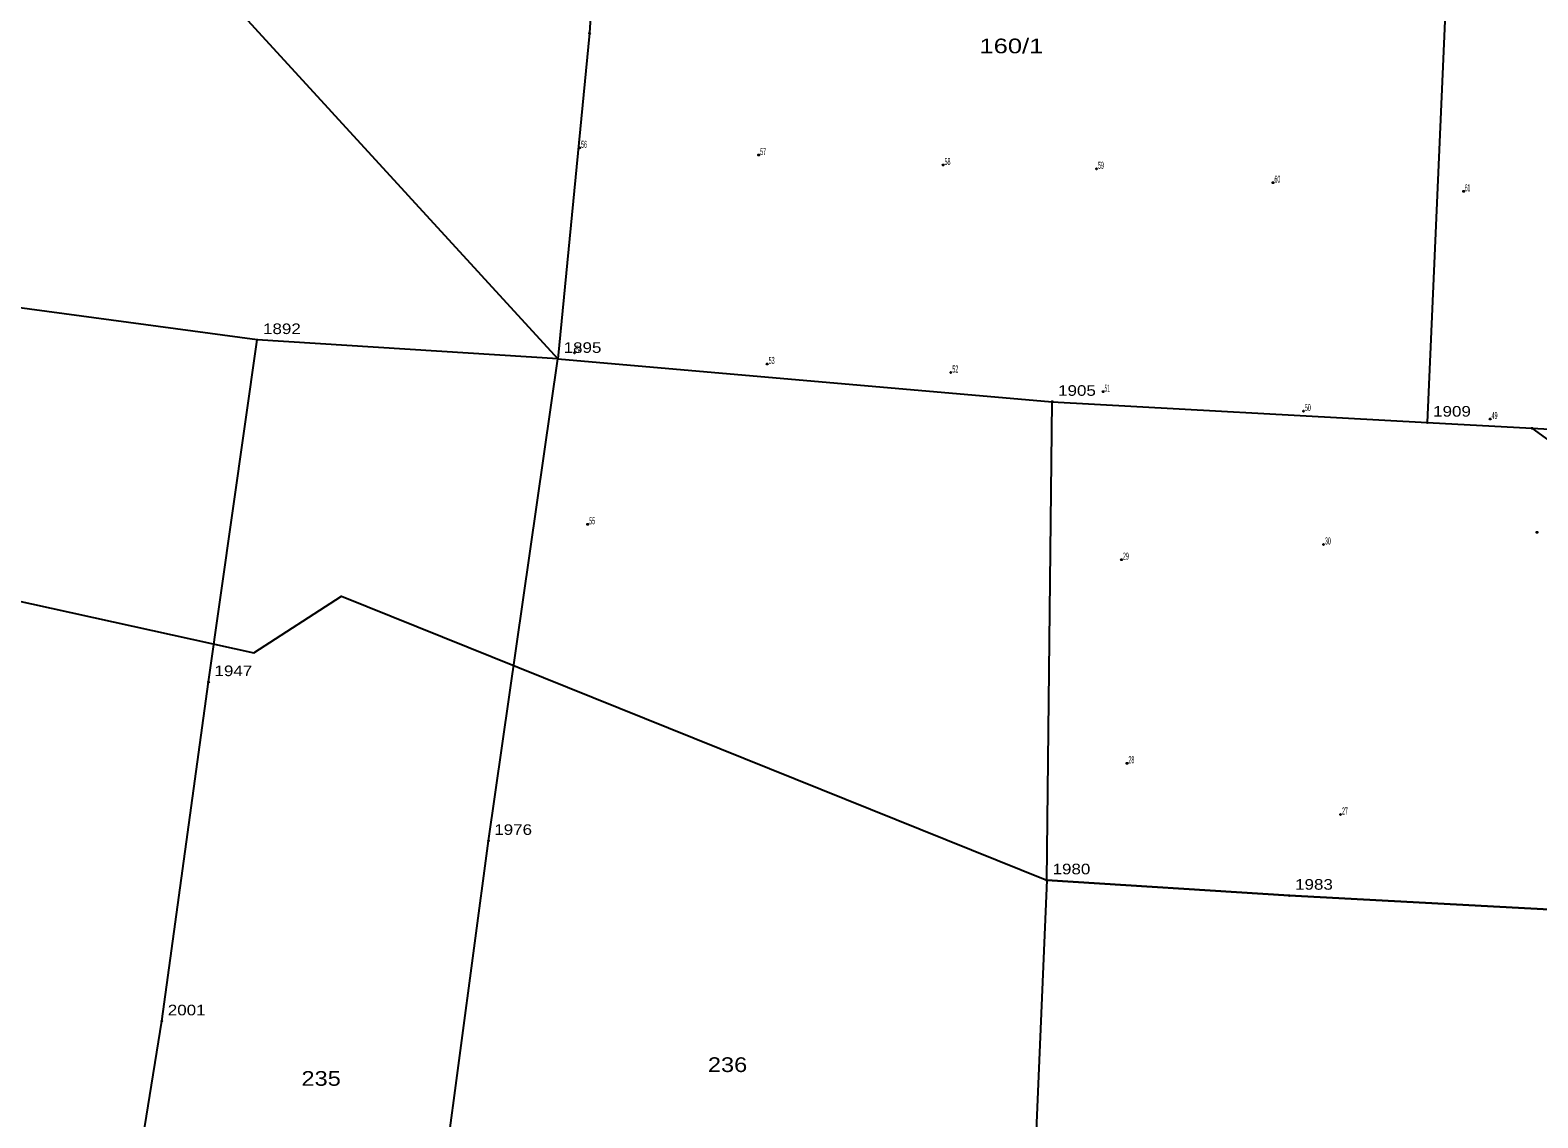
# Model space of a CAD drawing. Extents: x 4640203 to 4641683, y 5358965 to 5360242.
# Drawn here: x 4640893.3 to 4641021.5, y 5359880.5 to 5359973 of the extents above; entities that cross this region are included whole.
import ezdxf

# ---------------------------------------------------------------- set-up
doc = ezdxf.new("R2010")
doc.units = 0
doc.header["$LTSCALE"] = 0.36
doc.layers.add('24', color=7, linetype='Continuous')
for name, color, linetype, lineweight in [('25', 7, 'Continuous', 25), ('27', 7, 'Continuous', 25), ('63', 7, 'Continuous', 25), ('8', 7, 'Continuous', 25)]:
    doc.layers.add(name, color=color, linetype=linetype, lineweight=lineweight)

msp = doc.modelspace()

# ---------------------------------------------------------------- linework, layer by layer
at = {"layer": '25'}
msp.add_line((4640979.76, 5359900.7), (4640980.23, 5359941.38), dxfattribs=at)
for points in [[(4640943.53, 5360016.15), (4640940.88, 5359972.7), (4640938.17, 5359945.03)], [(4640895.32, 5359831.66), (4640897.94, 5359831.62), (4640905.57, 5359834.3), (4640924.34, 5359835), (4640924.95, 5359849.29), (4640932.27, 5359904.05), (4640938.17, 5359945.03), (4640912.6, 5359946.63)], [(4640938.17, 5359945.03), (4640980.23, 5359941.38), (4641012.13, 5359939.61)], [(4641090.44, 5359814.31), (4641093.89, 5359832.35), (4641094.08, 5359835.57), (4641095.72, 5359864.07), (4641093.76, 5359893.99), (4641082.34, 5359894.7), (4641048.93, 5359896.79), (4641032.54, 5359897.67), (4641000.39, 5359899.39), (4640979.76, 5359900.7), (4640978.53, 5359871.39), (4640977.73, 5359852.38), (4640977.07, 5359836.64)]]:
    msp.add_lwpolyline(points, dxfattribs=at)
for points in [[(4641012.13, 5359939.61), (4641021.04, 5359939.12), (4641069.42, 5359936.43), (4641068.41, 5359961.8), (4641067.93, 5359983.4), (4641067.87, 5359985.84), (4641044.14, 5359986.98), (4641021.21, 5359992.46), (4641014.65, 5359996.97)], [(4640846.34, 5359826.64), (4640871.59, 5359833.48), (4640895.32, 5359831.66), (4640900.86, 5359866.24), (4640904.5, 5359888.71), (4640908.47, 5359917.55), (4640912.6, 5359946.63), (4640876.8, 5359951.47), (4640871.4, 5359951.47), (4640867.89, 5359929.18), (4640860.08, 5359894.7), (4640851.26, 5359850.32), (4640850.53, 5359846.67), (4640847.65, 5359832.23), (4640846.77, 5359828.47)]]:
    msp.add_lwpolyline(points, close=True, dxfattribs=at)
at = {"layer": '27'}
for points in [[(4640899.67, 5359987.05), (4640938.17, 5359945.03), (4640980.23, 5359941.38), (4641012.13, 5359939.61), (4641021.04, 5359939.12), (4641082.34, 5359894.7), (4641125.28, 5359887.02), (4641158.69, 5359881.42)], [(4640641.2, 5359946.4), (4640662.1, 5359955.08), (4640682.79, 5359959.07), (4640685.79, 5359951.97), (4640721.09, 5359953.39), (4640750.46, 5359954.58), (4640781.35, 5359955.82), (4640790.81, 5359956.61), (4640790.2, 5359946.91), (4640912.32, 5359920.03), (4640919.77, 5359924.85), (4640979.76, 5359900.7), (4641000.39, 5359899.39), (4641032.54, 5359897.67), (4641072.49, 5359845.84)]]:
    msp.add_lwpolyline(points, dxfattribs=at)
at = {"layer": '63'}
for centre in [(4640940.03, 5359962.96), (4640940.03, 5359962.96), (4640955.26, 5359962.35), (4640955.26, 5359962.35), (4640970.95, 5359961.5), (4640970.95, 5359961.5), (4640984, 5359961.18), (4640984, 5359961.18), (4640999.01, 5359960), (4640999.01, 5359960), (4641015.23, 5359959.27), (4641015.23, 5359959.27), (4640939.59, 5359945.54), (4640939.59, 5359945.54), (4640955.99, 5359944.59), (4640955.99, 5359944.59), (4640971.61, 5359943.86), (4640971.61, 5359943.86), (4640984.57, 5359942.23), (4640984.57, 5359942.23), (4641001.6, 5359940.58), (4641001.6, 5359940.58), (4641017.48, 5359939.91), (4641017.48, 5359939.91), (4640940.72, 5359930.96), (4640940.72, 5359930.96), (4641021.47, 5359930.28), (4641021.47, 5359930.28), (4641003.3, 5359929.24), (4641003.3, 5359929.24), (4640986.12, 5359927.95), (4640986.12, 5359927.95), (4640986.59, 5359910.64), (4640986.59, 5359910.64), (4641004.75, 5359906.28), (4641004.75, 5359906.28)]:
    msp.add_circle(centre, 0.05, dxfattribs=at)
at = {"layer": '8'}
for centre in [(4640940.88, 5359972.7), (4640912.6, 5359946.63), (4640938.17, 5359945.03), (4640980.23, 5359941.38), (4641012.13, 5359939.61), (4641021.04, 5359939.12), (4640908.47, 5359917.55), (4640932.27, 5359904.05), (4640979.76, 5359900.7), (4641000.39, 5359899.39), (4640904.5, 5359888.71)]:
    msp.add_circle(centre, 0.045, dxfattribs=at)

# ---------------------------------------------------------------- texts
at = {"layer": '24'}
for s, width, p in [('160/1', 1.3, (4640974.04, 5359971)), ('236', 1.2, (4640950.94, 5359884.39)), ('235', 1.2, (4640916.37, 5359883.22))]:
    msp.add_text(s, height=1.25, dxfattribs=dict(at, width=width)).set_placement(p)
at = {"layer": '63'}
for s, width, p in [(' 56', 0.45, (4640940.03, 5359962.96)), (' 56', 0.45, (4640940.03, 5359962.96)), (' 57', 0.45, (4640955.26, 5359962.35)), (' 57', 0.45, (4640955.26, 5359962.35)), (' 58', 0.45, (4640970.95, 5359961.5)), (' 58', 0.45, (4640970.95, 5359961.5)), (' 59', 0.45, (4640984, 5359961.18)), (' 59', 0.45, (4640984, 5359961.18)), (' 60', 0.45, (4640999.01, 5359960)), (' 60', 0.45, (4640999.01, 5359960)), (' 61', 0.4, (4641015.23, 5359959.27)), (' 61', 0.4, (4641015.23, 5359959.27)), (' 54', 0.45, (4640939.59, 5359945.54)), (' 54', 0.45, (4640939.59, 5359945.54)), (' 53', 0.45, (4640955.99, 5359944.59)), (' 53', 0.45, (4640955.99, 5359944.59)), (' 52', 0.45, (4640971.61, 5359943.86)), (' 52', 0.45, (4640971.61, 5359943.86)), (' 51', 0.4, (4640984.57, 5359942.23)), (' 51', 0.4, (4640984.57, 5359942.23)), (' 50', 0.45, (4641001.6, 5359940.58)), (' 50', 0.45, (4641001.6, 5359940.58)), (' 49', 0.45, (4641017.48, 5359939.91)), (' 49', 0.45, (4641017.48, 5359939.91)), (' 55', 0.45, (4640940.72, 5359930.96)), (' 55', 0.45, (4640940.72, 5359930.96)), (' 30', 0.45, (4641003.3, 5359929.24)), (' 30', 0.45, (4641003.3, 5359929.24)), (' 29', 0.45, (4640986.12, 5359927.95)), (' 29', 0.45, (4640986.12, 5359927.95)), (' 28', 0.45, (4640986.59, 5359910.64)), (' 28', 0.45, (4640986.59, 5359910.64)), (' 27', 0.45, (4641004.75, 5359906.28)), (' 27', 0.45, (4641004.75, 5359906.28))]:
    msp.add_text(s, height=0.6, dxfattribs=dict(at, width=width)).set_placement(p)
at = {"layer": '8', "width": 1.2}
for s, p in [('1892', (4640913.1, 5359947.13)), ('1895', (4640938.67, 5359945.53)), ('1905', (4640980.73, 5359941.88)), ('1909', (4641012.63, 5359940.11)), ('1947', (4640908.97, 5359918.05)), ('1976', (4640932.77, 5359904.55)), ('1980', (4640980.26, 5359901.2)), ('1983', (4641000.89, 5359899.89)), ('2001', (4640905, 5359889.21))]:
    msp.add_text(s, height=0.9, dxfattribs=at).set_placement(p)

doc.saveas('drawing.dxf')
